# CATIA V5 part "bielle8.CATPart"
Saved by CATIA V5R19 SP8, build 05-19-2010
Part number: Pièce8
Bounding box of the stored display mesh (mm): x -81.907 to 20, y 35.038 to 98.687, z -15 to 19
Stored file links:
  G:\EU_thinkMotion\CFAO_2010\SIL_groupe1\SIL_groupe1\A reprendre\lalpha\lalpha\Alpha.mécanisme\bielle8.CATPart
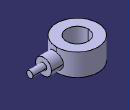
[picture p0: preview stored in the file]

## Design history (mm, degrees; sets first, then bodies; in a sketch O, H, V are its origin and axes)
Body1 (main body)
  Sketch1 on yz-plane, origin (0, 0, 0), H (0, 1, 0), V (0, 0, 1)
  Sketch2 on xy-plane, origin (0, 0, 0), H (1, 0, 0), V (0, 1, 0)
    circle A1 centre (-49.907, 66.8626) radius 16.7078
    circle A2 centre (-49.907, 66.8626) radius 32
  Pad1: profile Sketch2, direction (0, 0, 1), length 19, opposite side length 15
  Plane1: type Offset, RefPlane yz-plane, Offset 29, reversed
  Sketch3 on Plane1, origin (-29, 0, 0), H (0, 1, 0), V (0, 0, 1)
    circle A1 centre (63.4409, 0) radius 5
    point P1 (63.4409, 0)
    coincidence: P1 H
  Pad2: profile Sketch3, direction (1, 0, 0), length 49
  Sketch4 on Plane1, origin (-29, 0, 0), H (0, 1, 0), V (0, 0, 1)
    circle A1 centre (63.6797, 0) radius 12.4219
    point P1 (63.6797, 0)
    coincidence: P1 H
  Pad3: profile Sketch4, direction (1, 0, 0), length 28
